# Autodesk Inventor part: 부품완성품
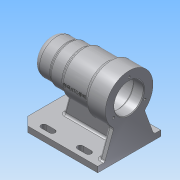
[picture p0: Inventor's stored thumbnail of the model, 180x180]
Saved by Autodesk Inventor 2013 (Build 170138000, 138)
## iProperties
Created: 2017-09
Part Number: 부품완성품
Material: 알루미늄 6061
Document SubType Name: Modeling
Designer: Administrator
Density: 2.71 g/cm^3
Mass: 697.075 g
Surface Area: 709.569 cm^2
Volume: 257.223 cm^3
Author: Administrator
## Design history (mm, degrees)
sketch "스케치1"
  geometry: L1 (-50, -45)-(50, -45); L2 (62, -33)-(62, 33); L3 (50, 45)-(-50, 45); L4 (-50, 45)-(-50, -45); L5 (50, 45)-(62, 33); L6 (62, -33)-(50, -45); 5 further points
  constraints: 12 end point, 4 point on line, 2 midpoint, 2 parallel, 1 horizontal, 1 horizontal alignment, 1 perpendicular, 1 vertical alignment
  dimensions: "d4" = 12 distance of L3.start point (62, 45); "d5" = 12 distance of L2.end point (62, 45) (= d4); "d6" = 12 distance of L2.start point (62, -45) (= d4); "d7" = 12 distance of L1.end point (62, -45) (= d6); "d8" = 112 distance between parallel lines of L2 L4; "d9" = 90 distance between parallel lines of L1 L3
extrude "돌출1" new body sketch "스케치1" distance "d10" = 8; taper "d11" = 0 deg
sketch "스케치2"
  geometry: L1 (-50, 0)-(-62, 0) reference; L2 (50, 0)-(-50, 0) reference; L3 (-50, 8)-(-62, 8) reference; L4 (50, 8)-(-50, 8) reference; L5 (-40, 8)-(-23.387, 70); L6 (-23.387, 70)-(50, 70); L7 (50, 70)-(50, 8); 1 further point
  constraints: 6 end point, 1 parallel, 1 perpendicular, 1 point on line
  dimensions: "d12" = 105 deg angle of L5 L4; "d13" = 22 distance of L5.start L3.end; "d14" = 62 distance between parallel lines of L4 L6
extrude "돌출2" join sketch "스케치2" stored distance "d15" = 8; taper "d16" = 0 deg
sketch "스케치3"
  geometry: L1 (0, 0)-(90, 0) reference; L2 (49, 8)-(90, 8) reference; L3 (0, 8)-(41, 8) reference; L4 (0, 0)-(0, 8) reference; L5 (10, 8)-(32.566, 70); L6 (32.566, 70)-(57.434, 70); L7 (57.434, 70)-(80, 8); L8 (10, 8)-(80, 8); 3 further points
  constraints: 8 end point, 2 midpoint, 2 point on line, 1 collinear, 1 equal length, 1 perpendicular, 1 vertical alignment
  dimensions: "d17" = 110 deg angle of L5 L3; "d18" = 10 distance of L5.start L3.start; "d19" = 62 distance between parallel lines of L3 L6
extrude "돌출3" join sketch "스케치3" distance "d20" = 8; taper "d21" = 0 deg
sketch "스케치5"
  geometry: L1 (50, 0)-(-50, 0) reference; L2 (50, 8)-(50, 70) reference; L3 (50, 0)-(50, 8) reference; L4 (-50, 0)-(-62, 0) reference; L5 (-62, 70)-(50, 70); L6 (50, 70)-(50, 104); L7 (50, 104)-(22, 104); L8 (22, 104)-(22, 100); L9 (22, 100)-(-17, 100); L10 (-17, 100)-(-17, 97); L11 (-17, 97)-(-37, 97); L12 (-37, 97)-(-37, 95); L13 (-37, 95)-(-62, 95); L14 (-62, 95)-(-62, 70); 1 further point
  constraints: 20 end point, 8 parallel, 2 perpendicular
  dimensions: "d31" = 70 distance from line of L1 L5.end; "d32" = 112 distance of L2.end L5.start; "d33" = 25 distance from line of L12.end L14; "d34" = 45 distance between parallel lines of L10 L14; "d35" = 84 distance between parallel lines of L8 L14; "d36" = 68 diameter of L7 L5; "d37" = 60 diameter of L9 L5; "d38" = 54 diameter of L11 L5; "d39" = 50 diameter of L13 L5; "d40" = 50 distance from line of L6 point (0, 0)
revolve "회전1" sketch "스케치5" stored, may be unused: angle "d41" = 90 deg
sketch "스케치8"
  geometry: L1 (-62, 45)-(-62, 95) reference; L2 (50, 43.992)-(50, 104) reference; L3 (-62, 70)-(50, 70); 2 further points
  constraints: 2 end point, 2 point on line, 1 midpoint, 1 perpendicular, 1 other
  dimensions: "d70" = 48 distance from line of point (2, 70) L2
feature "엠보싱1" sketch "스케치8" dims "d4" = 12, "d5" = 12 (= d4), "d6" = 12 (= d4), "d7" = 12 (= d6), "d8" = 112, "d9" = 90, "d12" = 105 deg, "d13" = 22, "d14" = 62, "d71" = 0.5, "d72" = 0
sketch "스케치6"
  geometry: L1 (-62, 45)-(-62, 95) reference; L2 (50, 43.992)-(50, 104) reference; L3 (-62, 70)-(50, 70); L4 (50, 91)-(35, 91); L5 (35, 91)-(35, 91); L6 (32, 94)-(-16, 94); L7 (-19, 91)-(-19, 91); L8 (-19, 91)-(-30.7, 91); L9 (-31, 90.7)-(-31, 87.5); L10 (-31, 87.5)-(-48.7, 87.5); L11 (-49, 87.2)-(-49, 86); L12 (-49, 86)-(-52.7, 86); L13 (-53, 85.7)-(-53, 80.5); L14 (-53, 80.5)-(-53, 80.5); L15 (-56, 77.5)-(-56, 70); A1 r 3 centre (32, 91) between (35, 91) and (32, 94); A2 r 3 centre (-16, 91) between (-16, 94) and (-19, 91); A3 r 3 centre (-53, 77.5) between (-53, 80.5) and (-56, 77.5); A4 r 0.3 centre (-52.7, 85.7) between (-52.7, 86) and (-53, 85.7); A5 r 0.3 centre (-48.7, 87.2) between (-48.7, 87.5) and (-49, 87.2); A6 r 0.3 centre (-30.7, 90.7) between (-30.7, 91) and (-31, 90.7); 7 further points
  constraints: 26 end point, 15 point on line, 12 point on circle, 12 tangent, 6 centre point, 6 parallel, 6 perpendicular, 4 equal radius, 1 collinear, 1 midpoint
  dimensions: "d42" = 15 distance of L4.start L4.end; "d44" = 54 distance of point (35, 94) point (-19, 94); "d45" = 12 distance of L7.end point (-31, 91); "d46" = 18 distance of L9.end point (-49, 87.5); "d47" = 4 distance of L11.end point (-53, 86); "d48" = 3 distance of L13.end point (-56, 80.5); "d49" = 48 diameter of L6 L3; "d50" = 42 diameter of L8 L3; "d51" = 35 diameter of L10 L3; "d52" = 32 diameter of L12 L3; "d53" = 21 diameter of L14 L3; "d54" = 42 diameter of L4 L3; "d55" = 3 radius of A1; "d56" = 0.3 radius of A4
revolve "회전2" sketch "스케치6" stored, may be unused: angle "d57" = 90 deg
sketch "스케치7" dims "d58" = 52
  geometry: C1 r 21 at (45, 70) reference; A1 r 34 centre (45, 70) between (66.9, 43.992) and (23.1, 43.992) reference; 3 further points
  constraints: 2 vertical alignment, 1 coincident, 2 other
hole "구멍1" sketch "스케치7" at (45, 96) diameter "d60" = 3.242; stored, may be unused: countersink angle "d64" = 90 deg, drill point angle "d66" = 118 deg; dims "d61" = 8, "d62" = 4, "d63" = 2, "d65" = 11
sketch "스케치9"
  geometry: L1 (50, 35)-(50, 45) reference; L2 (-40, 4)-(42, 4) reference; L3 (-38, 38)-(-26, 38); L4 (-26, 30)-(-38, 30); L5 (14, 38)-(26, 38); L6 (26, 30)-(14, 30); A1 r 4 centre (-26, 34) between (-26, 30) and (-26, 38); A2 r 4 centre (-38, 34) between (-38, 38) and (-38, 30); A3 r 4 centre (26, 34) between (26, 30) and (26, 38); A4 r 4 centre (14, 34) between (14, 38) and (14, 30); 1 further point
  constraints: 8 end point, 8 point on circle, 8 tangent, 4 centre point, 4 parallel, 1 collinear, 1 equal radius
  dimensions: "d73" = 34 vertical distance of A2.centre point (0, 0); "d74" = 12 distance of L3.start L3.end; "d75" = 4 radius of A2; "d76" = 40 distance of A1.centre A4.centre; "d77" = 24 distance from line of A3.centre L1; "d78" = 34 vertical distance of A3.centre point (0, 0)
extrude "돌출4" cut sketch "스케치9" distance "d79" = 10; taper "d80" = 0 deg
fillet "모깎기1" dims "d81" = 9
fillet "모깎기2" dims "d82" = 3
fillet "모깎기3" dims "d83" = 3
fillet "모깎기4" dims "d84" = 3
fillet "모깎기5" dims "d85" = 3
chamfer "모따기1" distance "d86" = 1; stored, may be unused: second distance "d87" = 2, angle "d88" = 45 deg
node "솔리드1"
pattern_circular "원형 패턴1" dims angle "d68" = 360 deg
mirror "대칭1"
